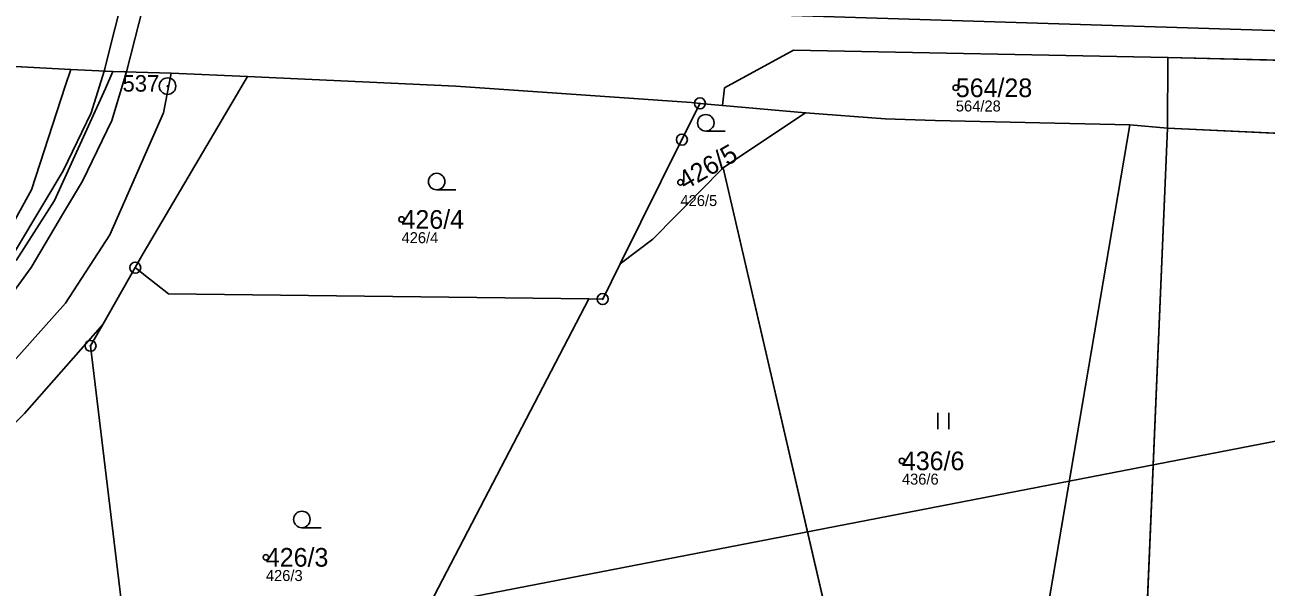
# Model space of a CAD drawing. Extents: x -732749 to -730903, y -1025757 to -1023435.
# Drawn here: x -732004.6 to -731891.6, y -1024858.7 to -1024807.5 of the extents above; entities that cross this region are included whole.
import ezdxf

# ---------------------------------------------------------------- set-up
doc = ezdxf.new("R2010")
doc.units = 0
for name, color, linetype in [('Definiční body', 7, 'Continuous'), ('Hranice parcel', 7, 'Continuous'), ('Parcelní čísla', 7, 'Continuous'), ('Polygon parcely', 7, 'Continuous'), ('Poz předměty', 7, 'Continuous'), ('Vnitřní kresba', 7, 'Continuous'), ('Věcná břemena k části', 7, 'Continuous'), ('Značky bodu BP', 7, 'Continuous'), ('Značky kultur', 7, 'Continuous')]:
    doc.layers.add(name, color=color, linetype=linetype)

msp = doc.modelspace()

# ---------------------------------------------------------------- linework, layer by layer
at = {"layer": 'Definiční body'}
for centre in [(-731919.82, -1024813.22), (-731944.89, -1024821.83), (-731970.28, -1024825.21), (-731924.73, -1024847.2), (-731982.63, -1024855.98)]:
    msp.add_circle(centre, 0.25, dxfattribs=at)
at = {"layer": 'Hranice parcel'}
for p, q in [((-732000.39, -1024811.54), (-732038.73, -1024809.48)), ((-731900.55, -1024816.9), (-731900.52, -1024810.45)), ((-731900.52, -1024810.45), (-731859.79, -1024811.49)), ((-731941.07, -1024814.82), (-731943.12, -1024814.64)), ((-731933.5, -1024815.5), (-731941.07, -1024814.82)), ((-731917.05, -1024893.6), (-731903.99, -1024816.58)), ((-731900.55, -1024816.9), (-731903.99, -1024816.58)), ((-731900.55, -1024816.9), (-731903.31, -1024881.74)), ((-731868.4, -1024818.39), (-731900.55, -1024816.9)), ((-731925.8, -1024886.1), (-731941, -1024820.5)), ((-731994.52, -1024829.6), (-731997.48, -1024834.78))]:
    msp.add_line(p, q, dxfattribs=at)
for points in [[(-731941.07, -1024814.82), (-731940.88, -1024813.23), (-731934.61, -1024809.8), (-731900.52, -1024810.45)], [(-732036.63, -1024854.43), (-732031.77, -1024850.7), (-732021.02, -1024843.65), (-732012.64, -1024835.51), (-732006.97, -1024827.91), (-732003.96, -1024822.5), (-732000.89, -1024813.06), (-732000.39, -1024811.54)], [(-732000.39, -1024811.54), (-731996.55, -1024811.75), (-731991.25, -1024811.9), (-731984.3, -1024812.2)], [(-731984.3, -1024812.2), (-731993.79, -1024828.31), (-731994.52, -1024829.6)], [(-731943.12, -1024814.64), (-731943.89, -1024814.57), (-731965.33, -1024813.06), (-731984.3, -1024812.2)], [(-731950.38, -1024829.25), (-731944.76, -1024817.94), (-731944.22, -1024816.86), (-731943.12, -1024814.64)], [(-731941, -1024820.5), (-731939.84, -1024819.73), (-731933.5, -1024815.5)], [(-731903.99, -1024816.58), (-731921.71, -1024816.21), (-731926.25, -1024816.04), (-731933.5, -1024815.5)], [(-731950.38, -1024829.25), (-731947.41, -1024827.01), (-731941, -1024820.5)], [(-731953.22, -1024832.45), (-731991.5, -1024831.97), (-731993.73, -1024830.22), (-731994.52, -1024829.6)], [(-731953.22, -1024832.45), (-731951.97, -1024832.46), (-731950.38, -1024829.25)], [(-731990.45, -1024904.2), (-731976.94, -1024878.45), (-731976.04, -1024876.27), (-731953.22, -1024832.45)], [(-731997.48, -1024834.78), (-732004.59, -1024842.88), (-732007.69, -1024845.91)], [(-731990.45, -1024904.2), (-731998.59, -1024836.72), (-731997.48, -1024834.78)]]:
    msp.add_lwpolyline(points, dxfattribs=at)
at = {"layer": 'Polygon parcely'}
for points in [[(-732038.73, -1024809.48), (-732000.39, -1024811.54), (-731996.55, -1024811.75), (-731991.25, -1024811.9), (-731984.3, -1024812.2), (-731965.33, -1024813.06), (-731943.89, -1024814.57), (-731943.12, -1024814.64), (-731941.07, -1024814.82), (-731940.88, -1024813.23), (-731934.61, -1024809.8), (-731900.52, -1024810.45), (-731859.79, -1024811.49), (-731771.86, -1024814.04), (-731771.91, -1024821.54), (-731740.64, -1024822.2), (-731676.03, -1024823.7), (-731674.8, -1024820.19), (-731643.83, -1024820.12)], [(-732004.59, -1024842.88), (-731997.48, -1024834.78), (-731994.52, -1024829.6), (-731993.79, -1024828.31), (-731984.3, -1024812.2), (-731991.25, -1024811.9), (-731996.55, -1024811.75), (-732000.39, -1024811.54), (-732000.89, -1024813.06), (-732003.96, -1024822.5), (-732006.97, -1024827.91)]]:
    msp.add_lwpolyline(points, dxfattribs=at)
for points in [[(-732021.02, -1024843.65), (-732012.64, -1024835.51), (-732006.97, -1024827.91), (-732003.96, -1024822.5), (-732000.89, -1024813.06), (-732000.39, -1024811.54), (-732038.73, -1024809.48), (-732038.47, -1024813.73), (-732036.77, -1024851.15), (-732036.63, -1024854.43), (-732031.77, -1024850.7)], [(-731900.55, -1024816.9), (-731900.52, -1024810.45), (-731934.61, -1024809.8), (-731940.88, -1024813.23), (-731941.07, -1024814.82), (-731933.5, -1024815.5), (-731926.25, -1024816.04), (-731921.71, -1024816.21), (-731903.99, -1024816.58)], [(-731859.79, -1024811.49), (-731900.52, -1024810.45), (-731900.55, -1024816.9), (-731868.4, -1024818.39), (-731859.97, -1024818.66)], [(-731950.38, -1024829.25), (-731944.76, -1024817.94), (-731944.22, -1024816.86), (-731943.12, -1024814.64), (-731943.89, -1024814.57), (-731965.33, -1024813.06), (-731984.3, -1024812.2), (-731993.79, -1024828.31), (-731994.52, -1024829.6), (-731993.73, -1024830.22), (-731991.5, -1024831.97), (-731953.22, -1024832.45), (-731951.97, -1024832.46)], [(-731950.38, -1024829.25), (-731947.41, -1024827.01), (-731941, -1024820.5), (-731939.84, -1024819.73), (-731933.5, -1024815.5), (-731941.07, -1024814.82), (-731943.12, -1024814.64), (-731944.22, -1024816.86), (-731944.76, -1024817.94)], [(-731921.71, -1024816.21), (-731926.25, -1024816.04), (-731933.5, -1024815.5), (-731939.84, -1024819.73), (-731941, -1024820.5), (-731925.8, -1024886.1), (-731917.05, -1024893.6), (-731903.99, -1024816.58)], [(-731900.55, -1024816.9), (-731903.99, -1024816.58), (-731917.05, -1024893.6), (-731903.31, -1024881.74)], [(-731868.07, -1024842.53), (-731866.93, -1024820.09), (-731868.4, -1024818.39), (-731900.55, -1024816.9), (-731903.31, -1024881.74), (-731897.27, -1024876.45), (-731869.15, -1024859.4)], [(-731941, -1024820.5), (-731947.41, -1024827.01), (-731950.38, -1024829.25), (-731951.97, -1024832.46), (-731953.22, -1024832.45), (-731976.04, -1024876.27), (-731976.94, -1024878.45), (-731990.45, -1024904.2), (-731964.45, -1024896.92), (-731944.61, -1024891.37), (-731925.8, -1024886.1)], [(-731991.5, -1024831.97), (-731993.73, -1024830.22), (-731994.52, -1024829.6), (-731997.48, -1024834.78), (-731998.59, -1024836.72), (-731990.45, -1024904.2), (-731976.94, -1024878.45), (-731976.04, -1024876.27), (-731953.22, -1024832.45)], [(-732021.92, -1024971.69), (-732014.97, -1024957.61), (-732013.75, -1024954.87), (-732006.12, -1024937.77), (-731998.64, -1024920.91), (-731990.45, -1024904.2), (-731998.59, -1024836.72), (-731997.48, -1024834.78), (-732004.59, -1024842.88), (-732007.69, -1024845.91), (-732014.33, -1024852.39), (-732025.07, -1024859.76), (-732027.53, -1024861.64), (-732032.52, -1024865.46), (-732037.13, -1024868.99), (-732026.66, -1024955.63), (-732023.84, -1024979)]]:
    msp.add_lwpolyline(points, close=True, dxfattribs=at)
at = {"layer": 'Poz předměty'}
for p, q in [((-731875.24, -1024808.51), (-731989.44, -1024804.92)), ((-731882.7, -1024843.85), (-731964.79, -1024859.75))]:
    msp.add_line(p, q, dxfattribs=at)
at = {"layer": 'Vnitřní kresba'}
for p, q in [((-731996.55, -1024811.75), (-731997.24, -1024813.29)), ((-731991.94, -1024815.5), (-731991.25, -1024811.9)), ((-731997.24, -1024813.29), (-732001.86, -1024823.49)), ((-731996.83, -1024826.62), (-731991.94, -1024815.5)), ((-732001.86, -1024823.49), (-732005.35, -1024828.94)), ((-732000.86, -1024832.82), (-731996.83, -1024826.62)), ((-732007.33, -1024840.05), (-732000.86, -1024832.82))]:
    msp.add_line(p, q, dxfattribs=at)
at = {"layer": 'Věcná břemena k části'}
for points in [[(-731997.36, -1024811.71), (-731996.55, -1024811.75), (-731995.32, -1024811.78), (-731993.45, -1024804.37), (-731992.57, -1024798.69), (-731991.28, -1024783.13), (-731992.75, -1024783.5), (-731993.33, -1024783.56), (-731994.56, -1024798.45), (-731995.41, -1024803.97)], [(-732032.46, -1024852.67), (-732031.29, -1024854.3), (-732021.9, -1024847.58), (-732016.19, -1024843.13), (-732011.82, -1024839.05), (-732007.63, -1024834.57), (-732004, -1024829.6), (-732001.04, -1024824.61), (-731999.31, -1024821.73), (-731996.64, -1024816.21), (-731995.32, -1024811.78), (-731996.55, -1024811.75), (-731997.36, -1024811.71), (-731998.52, -1024815.51), (-732001.07, -1024820.77), (-732002.76, -1024823.59), (-732005.68, -1024828.5), (-732009.17, -1024833.29), (-732013.24, -1024837.63), (-732017.49, -1024841.61), (-732023.1, -1024845.98)]]:
    msp.add_lwpolyline(points, close=True, dxfattribs=at)
at = {"layer": 'Značky bodu BP'}
for centre, radius in [((-731991.58, -1024813.07), 0.75), ((-731991.58, -1024813.07), 0.03), ((-731943.12, -1024814.64), 0.5), ((-731943.12, -1024814.64), 0.0303), ((-731944.76, -1024817.94), 0.5), ((-731944.76, -1024817.94), 0.0303), ((-731994.52, -1024829.6), 0.5), ((-731994.52, -1024829.6), 0.0303), ((-731951.97, -1024832.46), 0.5), ((-731951.97, -1024832.46), 0.0303), ((-731998.59, -1024836.72), 0.5), ((-731998.59, -1024836.72), 0.0303)]:
    msp.add_circle(centre, radius, dxfattribs=at)
at = {"layer": 'Značky kultur'}
for p, q in [((-731942.58, -1024817.16), (-731940.83, -1024817.16)), ((-731967.08, -1024822.51), (-731965.33, -1024822.51)), ((-731921.46, -1024844.31), (-731921.46, -1024842.81)), ((-731920.46, -1024844.31), (-731920.46, -1024842.81)), ((-731979.35, -1024853.28), (-731977.6, -1024853.28))]:
    msp.add_line(p, q, dxfattribs=at)
for centre in [(-731942.58, -1024816.41), (-731967.08, -1024821.76), (-731979.35, -1024852.53)]:
    msp.add_circle(centre, 0.75, dxfattribs=at)

# ---------------------------------------------------------------- texts
at = {"layer": 'Definiční body'}
for s, p in [('564/28', (-731919.82, -1024815.38)), ('426/5', (-731944.89, -1024823.99)), ('426/4', (-731970.28, -1024827.37)), ('436/6', (-731924.73, -1024849.36)), ('426/3', (-731982.63, -1024858.14))]:
    msp.add_text(s, height=1, dxfattribs=at).set_placement(p)
at = {"layer": 'Parcelní čísla'}
for s, p in [('564/28', (-731919.82, -1024814.07)), ('426/4', (-731970.28, -1024826.06)), ('436/6', (-731924.73, -1024848.05)), ('426/3', (-731982.63, -1024856.83))]:
    msp.add_text(s, height=1.7, dxfattribs=at).set_placement(p)
msp.add_text('426/5', height=1.7, rotation=30, dxfattribs=at).set_placement((-731944.46, -1024822.57))
at = {"layer": 'Značky bodu BP'}
msp.add_text('537', height=1.5, dxfattribs=at).set_placement((-731995.68, -1024813.57))

doc.saveas('drawing.dxf')
